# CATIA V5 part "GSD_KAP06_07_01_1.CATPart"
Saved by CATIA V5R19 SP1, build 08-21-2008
Part number: GSD_SWEEP_EXPLICIT
Definition: Beispielmodell für die Funktion Translation - Explizit / Sweep - Explicit.
Description: CATIA V5 Flächenmodellierung  Copyright (c) 2009 Maik Hertha IT Consultants
Bounding box of the stored display mesh (mm): x -129.496 to 153.827, y -114.965 to 1.371, z -3.561 to 35.389
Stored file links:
  \GSD_BUCH_UEBUNG\GSD_KAP06_07_01_1.CATPart
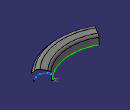
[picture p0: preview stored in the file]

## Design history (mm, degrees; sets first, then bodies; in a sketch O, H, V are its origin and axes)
AxisSystem1 "Absolute Axis System": origin (0, 0, 0), X (1, 0, 0), Y (0, 1, 0), Z (0, 0, 1)
Set1
  Sketch1 on XY plane of AxisSystem1, origin (0, 0, 0), H (1, 0, 0), V (0, 1, 0)
    spline S1 through (-84.4402, 28.3163) (-41.9975, 13.9992) (16.6726, -3.8633) (83.1477, 26.0664)
    arc A1 centre (-12.5654, 127.5678) radius 184.0903 from (-101.3193, -33.7146) to (113.7312, -6.3666) ccw
    point P2 (-101.3193, -33.7146)
    curve C1
    curve C2
    construction line L1 (113.7312, -6.3666) -> (68.543, 41.5543)
    construction line L2 (113.7312, -6.3666) -> (148.8891, 26.7864)
    construction line L3 (-84.4402, 28.3163) -> (-126.2849, 39.7026)
    point P6 (-84.4402, 28.3163)
    construction line L4 (-84.4402, 28.3163) -> (-102.8926, -39.4963)
    point P9 (83.1477, 26.0664)
    point P10 (-84.4402, 28.3163)
    perpendicularity: L2 L1, L4 L3
    tangency: A1 L2, L3 S1
    coincidence: L1 P9, P10 P6, P2 L4
  Plane1: type Normal, Curve Sketch1.C2, RefPoint {point type OnCurve, Support Sketch1.C1, Ratio 1}
  Sketch2 on Plane1, origin (113.7312, -6.3666, 0), H (0.6861, -0.7275, 0), V (0, 0, 1)
    point P1 (-10.6349, 0)
    line L1 (-10.6349, 0) -> (2.453, 19.9771)
    line L2 (13.2775, 24.1898) -> (34.8345, 18.7192)
    line L3 (47.2539, 7.6111) -> (51.4574, -3.5606)
    arc A1 centre (10.8177, 14.497) radius 10 from (2.453, 19.9771) to (13.2775, 24.1898) cw
    arc A2 centre (30.407, 1.2722) radius 18 from (34.8345, 18.7192) to (47.2539, 7.6111) cw
    curve C1
    line L4 (58.6057, -2.3035) -> (-22.3418, 21.9357)
    curve C2
    radius A2 = 18
    radius A1 = 10
    coincidence: P1 H
    tangency: A1 L1, A1 L2, A2 L2, A2 L3
  Point1: type OnCurve, Support Sketch2.C1, Ratio 1
  Point2: type OnCurve, Support Sketch2.C1, Ratio 0
  Sweep1: type Unspec, Guide Sketch1.C2, PullingDir (0, 0, 1), AngleRef 20, Profile Sketch2.C1
Body1 (main body)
